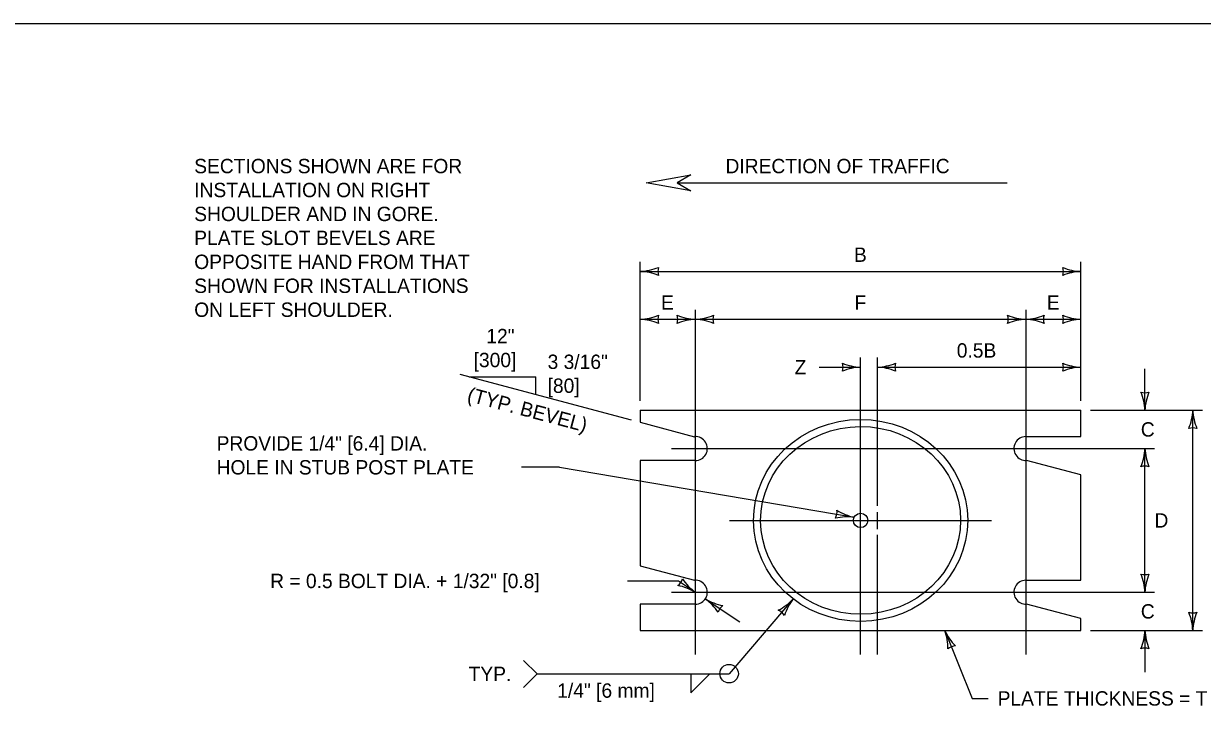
# Model space of a CAD drawing. Extents: x 49991 to 81321, y 49988 to 50028.
# Drawn here: x 50005.489 to 50010.412, y 49996.092 to 49998.999 of the extents above; entities that cross this region are included whole.
import ezdxf

# ---------------------------------------------------------------- set-up
doc = ezdxf.new("R2010")
doc.units = 0
for name, color, linetype in [('Level 1', 7, 'Continuous'), ('Level 2', 7, 'Continuous'), ('Level 3', 7, 'Continuous'), ('Level 5', 7, 'Continuous')]:
    doc.layers.add(name, color=color, linetype=linetype)

msp = doc.modelspace()

# ---------------------------------------------------------------- linework, layer by layer
at = {"layer": 'Level 1'}
for p, q in [((50008.0643, 49997.3838), (50009.9043, 49997.3838)), ((50008.0643, 49997.3838), (50008.0643, 49997.3338)), ((50009.9043, 49997.2738), (50009.9043, 49997.3838)), ((50008.0643, 49997.3338), (50008.2913, 49997.2735)), ((50009.6743, 49997.2738), (50009.9043, 49997.2738)), ((50008.2943, 49997.1738), (50008.0643, 49997.1738)), ((50008.0643, 49997.1738), (50008.0643, 49996.7338)), ((50009.9043, 49997.1138), (50009.6773, 49997.1741)), ((50009.9043, 49996.6738), (50009.9043, 49997.1138)), ((50008.0643, 49996.7338), (50008.2913, 49996.6735)), ((50009.6743, 49996.6738), (50009.9043, 49996.6738)), ((50008.2943, 49996.5738), (50008.0643, 49996.5738)), ((50008.0643, 49996.5738), (50008.0643, 49996.4638)), ((50009.9043, 49996.5138), (50009.6773, 49996.5741)), ((50009.9043, 49996.4638), (50009.9043, 49996.5138)), ((50008.0643, 49996.4638), (50009.9043, 49996.4638))]:
    msp.add_line(p, q, dxfattribs=at)
msp.add_lwpolyline([(49999.3835, 49998.9992), (50016.7501, 49998.9992), (50016.7501, 49987.7988), (49999.3835, 49987.7988)], close=True, dxfattribs=at)
msp.add_circle((50008.9843, 49996.9238), 0.03, dxfattribs=at)
for centre, start, end in [((50008.2943, 49997.2238), 270, 93.4543), ((50009.6743, 49997.2238), 90, 273.4543), ((50008.2943, 49996.6238), 270, 93.4543), ((50009.6743, 49996.6238), 90, 273.4543)]:
    msp.add_arc(centre, 0.05, start, end, dxfattribs=at)
for major_axis, ratio in [((0.4473, 0.0014), 0.943308), ((0.4175, 0.0014), 0.939269)]:
    msp.add_ellipse((50008.9843, 49996.9238), major_axis=major_axis, ratio=ratio, dxfattribs=at)
at = {"layer": 'Level 3'}
for p, q in [((50008.2186, 49998.334), (50009.596, 49998.334)), ((50008.0643, 49997.4238), (50008.0643, 49998.0038)), ((50009.9043, 49997.4238), (50009.9043, 49998.0038)), ((50008.0643, 49997.9638), (50009.9043, 49997.9638)), ((50008.0643, 49997.7638), (50008.2943, 49997.7638)), ((50008.2943, 49997.7638), (50009.6757, 49997.7638)), ((50009.6757, 49997.7638), (50009.9043, 49997.7638)), ((50008.8109, 49997.5638), (50008.9843, 49997.5638)), ((50009.0543, 49996.9844), (50009.0543, 49997.6038)), ((50009.0543, 49997.5638), (50009.9043, 49997.5638)), ((50010.1716, 49997.3838), (50010.1716, 49997.5572)), ((50007.311, 49997.534), (50008.0257, 49997.3442)), ((50007.3495, 49997.5238), (50007.6278, 49997.5238)), ((50007.6278, 49997.4512), (50007.6278, 49997.5238)), ((50009.9443, 49997.3838), (50010.4116, 49997.3838)), ((50010.3716, 49996.4638), (50010.3716, 49997.3838)), ((50010.1716, 49996.6238), (50010.1716, 49997.2238)), ((50007.7267, 49997.1456), (50007.5684, 49997.1456)), ((50007.7267, 49997.1456), (50008.9574, 49996.937)), ((50009.0543, 49996.8872), (50009.0543, 49996.9586)), ((50009.0543, 49996.3638), (50009.0543, 49996.8629)), ((50008.0111, 49996.6709), (50008.2235, 49996.6709)), ((50008.2235, 49996.6709), (50008.2943, 49996.6238)), ((50008.3359, 49996.5961), (50008.4803, 49996.5)), ((50008.7029, 49996.5957), (50008.4351, 49996.2836)), ((50009.3363, 49996.4638), (50009.45, 49996.1803)), ((50009.9443, 49996.4638), (50010.4116, 49996.4638)), ((50010.1716, 49996.4638), (50010.1716, 49996.2904)), ((50007.6337, 49996.2826), (50007.5771, 49996.3392)), ((50007.6337, 49996.2826), (50007.5771, 49996.226)), ((50007.6337, 49996.2826), (50008.4351, 49996.2836)), ((50008.2751, 49996.2836), (50008.2751, 49996.2036)), ((50008.2751, 49996.2036), (50008.3551, 49996.2836)), ((50009.45, 49996.1803), (50009.5165, 49996.1803))]:
    msp.add_line(p, q, dxfattribs=at)
msp.add_lwpolyline([(50008.2755, 49998.3012), (50008.0893, 49998.334), (50008.2755, 49998.367), (50008.2187, 49998.334)], close=True, dxfattribs=at)
msp.add_circle((50008.4352, 49996.2836), 0.0387, dxfattribs=at)
for centre, radius, start, end in [((50008.0528, 49998.1965), 0.233, 272.8273, 292.0772), ((50008.0551, 49997.7417), 0.2223, 67.456, 87.6395), ((50008.1925, 49997.9638), 0.0548, 162.1388, 197.8612), ((50009.9135, 49998.1859), 0.2223, 247.456, 267.6395), ((50009.7761, 49997.9638), 0.0548, 342.1388, 17.8612), ((50009.9158, 49997.7311), 0.233, 92.8273, 112.0772), ((50008.0528, 49997.9965), 0.233, 272.8273, 292.0772), ((50008.0551, 49997.5417), 0.2223, 67.456, 87.6395), ((50008.1925, 49997.7638), 0.0548, 162.1388, 197.8612), ((50008.3035, 49997.9859), 0.2223, 247.456, 267.6395), ((50008.1661, 49997.7638), 0.0548, 342.1388, 17.8612), ((50008.3058, 49997.5311), 0.233, 92.8273, 112.0772), ((50008.2828, 49997.9965), 0.233, 272.8273, 292.0772), ((50008.2851, 49997.5417), 0.2223, 67.456, 87.6395), ((50008.4225, 49997.7638), 0.0548, 162.1388, 197.8612), ((50009.6835, 49997.9859), 0.2223, 247.456, 267.6395), ((50009.5461, 49997.7638), 0.0548, 342.1388, 17.8612), ((50009.6858, 49997.5311), 0.233, 92.8273, 112.0772), ((50009.6628, 49997.9965), 0.233, 272.8273, 292.0772), ((50009.6651, 49997.5417), 0.2223, 67.456, 87.6395), ((50009.8025, 49997.7638), 0.0548, 162.1388, 197.8612), ((50009.9135, 49997.9859), 0.2223, 247.456, 267.6395), ((50009.7761, 49997.7638), 0.0548, 342.1388, 17.8612), ((50009.9158, 49997.5311), 0.233, 92.8273, 112.0772), ((50008.9935, 49997.7859), 0.2223, 247.456, 267.6395), ((50008.8561, 49997.5638), 0.0548, 342.1388, 17.8612), ((50008.9958, 49997.3311), 0.233, 92.8273, 112.0772), ((50009.0428, 49997.7965), 0.233, 272.8273, 292.0772), ((50009.0451, 49997.3417), 0.2223, 67.456, 87.6395), ((50009.1825, 49997.5638), 0.0548, 162.1388, 197.8612), ((50009.9135, 49997.7859), 0.2223, 247.456, 267.6395), ((50009.7761, 49997.5638), 0.0548, 342.1388, 17.8612), ((50009.9158, 49997.3311), 0.233, 92.8273, 112.0772), ((50010.1716, 49997.512), 0.0548, 252.1388, 287.8612), ((50009.9389, 49997.3723), 0.233, 2.8273, 22.0772), ((50010.3937, 49997.3746), 0.2223, 157.456, 177.6395), ((50010.1495, 49997.393), 0.2223, 337.456, 357.6395), ((50010.6043, 49997.3953), 0.233, 182.8273, 202.0772), ((50010.3716, 49997.2556), 0.0548, 72.1388, 107.8612), ((50009.9495, 49997.233), 0.2223, 337.456, 357.6395), ((50010.4043, 49997.2353), 0.233, 182.8273, 202.0772), ((50010.1716, 49997.0956), 0.0548, 72.1388, 107.8612), ((50008.831, 49996.9584), 0.0548, 332.5179, 8.2403), ((50008.9298, 49996.7056), 0.233, 83.2064, 102.4563), ((50009.0035, 49997.1545), 0.2223, 237.8351, 258.0186), ((50008.1875, 49996.6948), 0.0548, 308.5221, 344.2444), ((50008.4249, 49996.8037), 0.2223, 213.8393, 234.0228), ((50010.1716, 49996.752), 0.0548, 252.1388, 287.8612), ((50009.9389, 49996.6123), 0.233, 2.8273, 22.0772), ((50010.3937, 49996.6146), 0.2223, 157.456, 177.6395), ((50008.175, 49996.4236), 0.233, 59.2106, 78.4604), ((50008.2051, 49996.4163), 0.2223, 33.7659, 53.9495), ((50008.4554, 49996.7961), 0.233, 239.1372, 258.3871), ((50008.5402, 49996.7473), 0.2223, 296.8311, 317.0146), ((50008.887, 49996.4529), 0.233, 142.2024, 161.4523), ((50008.4426, 49996.5249), 0.0548, 128.4488, 164.1711), ((50008.6194, 49996.4984), 0.0548, 31.5139, 67.2363), ((50010.3716, 49996.592), 0.0548, 252.1388, 287.8612), ((50010.1389, 49996.4523), 0.233, 2.8273, 22.0772), ((50010.5937, 49996.4546), 0.2223, 157.456, 177.6395), ((50009.1267, 49996.3896), 0.2223, 359.3094, 19.4929), ((50009.548, 49996.5611), 0.233, 204.6807, 223.9305), ((50009.9495, 49996.473), 0.2223, 337.456, 357.6395), ((50010.4043, 49996.4753), 0.233, 182.8273, 202.0772), ((50009.384, 49996.3448), 0.0548, 93.9922, 129.7145), ((50010.1716, 49996.3356), 0.0548, 72.1388, 107.8612)]:
    msp.add_arc(centre, radius, start, end, dxfattribs=at)
at = {"layer": 'Level 5'}
for p, q in [((50008.2943, 49996.3638), (50008.2943, 49997.8038)), ((50009.6743, 49997.8038), (50009.6743, 49996.3638)), ((50008.9843, 49996.3638), (50008.9843, 49997.6038)), ((50008.1943, 49997.2238), (50010.2116, 49997.2238)), ((50008.437, 49996.9238), (50009.5316, 49996.9238)), ((50008.1943, 49996.6238), (50010.2116, 49996.6238))]:
    msp.add_line(p, q, dxfattribs=at)

# ---------------------------------------------------------------- texts
at = {"layer": 'Level 2'}
for s, p in [('SECTIONS SHOWN ARE FOR', (50006.2016, 49998.374)), ('DIRECTION OF TRAFFIC', (50008.4202, 49998.374)), ('INSTALLATION ON RIGHT', (50006.2016, 49998.274)), ('SHOULDER AND IN GORE.', (50006.2016, 49998.174)), ('PLATE SLOT BEVELS ARE', (50006.2016, 49998.074)), ('B', (50008.9566, 49998.0038)), ('OPPOSITE HAND FROM THAT', (50006.2016, 49997.974)), ('SHOWN FOR INSTALLATIONS', (50006.2016, 49997.874)), ('E', (50008.1506, 49997.8038)), ('F', (50008.9589, 49997.8038)), ('E', (50009.762, 49997.8038)), ('ON LEFT SHOULDER.', (50006.2016, 49997.774)), ('12"', (50007.4214, 49997.6638)), ('0.5B', (50009.3859, 49997.6038)), ('[300]', (50007.3684, 49997.5638)), ('3 3/16"', (50007.6773, 49997.5564)), ('Z', (50008.7086, 49997.5338)), ('[80]', (50007.6773, 49997.4564)), ('C', (50010.1544, 49997.2738)), ('PROVIDE 1/4" [6.4] DIA.', (50006.2952, 49997.2156)), ('HOLE IN STUB POST PLATE', (50006.2952, 49997.1156)), ('D', (50010.2116, 49996.8938)), ('R = 0.5 BOLT DIA. + 1/32" [0.8]', (50006.5188, 49996.6409)), ('C', (50010.1544, 49996.5138)), ('TYP.', (50007.3475, 49996.2526)), ('1/4" [6 mm]', (50007.7176, 49996.1831)), ('PLATE THICKNESS = T', (50009.5565, 49996.1503))]:
    msp.add_text(s, height=0.06, dxfattribs=at).set_placement(p)
msp.add_text('(TYP. BEVEL)', height=0.059999, rotation=345.1202, dxfattribs=at).set_placement((50007.3379, 49997.4234))

doc.saveas('drawing.dxf')
